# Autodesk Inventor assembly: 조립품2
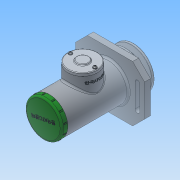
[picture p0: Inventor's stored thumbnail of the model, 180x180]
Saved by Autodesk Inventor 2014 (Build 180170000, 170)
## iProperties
Created: 2017-10
Part Number: 조립품2
Document SubType Name: Assembly
Designer: net
Author: net
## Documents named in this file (19)
- C:\Users\net\Desktop\471007V1017\조립품2.iam
- C:\Users\net\Desktop\471007V1017\본체.ipt
- C:\Users\net\Desktop\471007V1017\사이드 커버.ipt
- 사이드 커버.ipt
- C:\Users\net\Desktop\471007V1017\축.ipt
- C:\Users\net\Desktop\471007V1017\멈춤링 35x1.6.ipt
- C:\Users\net\Desktop\471007V1017\베어링 15 x 35 x 11.ipt
- C:\Users\net\Desktop\471007V1017\부시1.ipt
- C:\Users\net\Desktop\471007V1017\부시2.ipt
- C:\Users\net\Desktop\471007V1017\와셔 10x21.ipt
- C:\Users\net\Desktop\471007V1017\너트 M10.ipt
- C:\Users\net\Desktop\471007V1017\오일 실 15 25 7.ipt
- C:\Users\net\Desktop\471007V1017\키 4 x 4 x 18.ipt
- C:\Users\net\Desktop\471007V1017\V-벨트풀리.ipt
- C:\Users\net\Desktop\471007V1017\와셔 4x16.ipt
- C:\Users\net\Desktop\471007V1017\볼트 M4 x 10.ipt
- C:\Users\net\Desktop\471007V1017\탑 커버.ipt
- C:\Users\net\Desktop\471007V1017\와셔 3x6.ipt
- C:\Users\net\Desktop\471007V1017\십자볼트 M3 x 10.ipt
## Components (2 placed, 2 different names)
1. V-벨트풀리:1
2. ISO 4017 M4 x 10:1
